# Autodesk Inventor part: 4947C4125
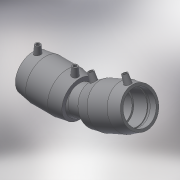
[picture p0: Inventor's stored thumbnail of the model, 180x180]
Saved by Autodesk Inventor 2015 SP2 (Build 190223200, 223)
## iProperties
Created: 2017-06
Part Number: 4947C4125
Material: Generic
Description: PLASSON ADJUSTABLE ELBOW 125
Document SubType Name: Modeling
Designer: KIM
Mass: 55.0731 g
Surface Area: 148.067 cm^2
Volume: 55.0731 cm^3
Density: 1 g/cm^3
Appearance: Default
Author: KIM
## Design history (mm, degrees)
derived "4947C4.ipt"
feature "Solid1::4947C4.ipt"
tag "TaggingFeature1"
body "Solid1"
other parameters: "d0" = 152.8, "d2" = 157, "d3" = 85, "d4" = 42.5, "d5" = 141.3, "d7" = 125, "d8" = 168 deg, "d10" = 34, "d11" = 11.33333, "d29" = 95, "d30" = 15, "d31" = 61.12, "d34" = 5 deg, "d41" = 4, "d42" = 14, "d43" = 0, "d48" = 112.5, "d49" = 24 deg, "d50" = 382, "d51" = 78 deg, "d52" = 90 deg, "d55" = 33.9, "d57" = 168 deg, "d58" = 6.78, "d60" = 43.02259, "d62" = 3, "d63" = 0, "d_" = 125, "L_" = 382, "L_1" = 85, "D_" = 157, "A_" = 95, "d_2" = 12, "L_0" = 148, "d54" = 67.8, "d59" = 143.40864
